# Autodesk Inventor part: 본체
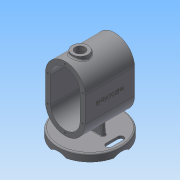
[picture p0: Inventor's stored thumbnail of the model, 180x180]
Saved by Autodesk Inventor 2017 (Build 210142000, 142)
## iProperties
Created: 2016-12
Part Number: 본체
Material: 알루미늄 6061
Document SubType Name: Modeling
Designer: mduedu
Density: 2.71 g/cm^3
Appearance: 기본값
Mass: 1098.88 g
Surface Area: 1080.91 cm^2
Volume: 405.491 cm^3
Author: mduedu
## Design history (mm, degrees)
sketch "스케치1"
  geometry: L1 (40, -25)-(40, 25); L2 (-40, 25)-(-40, -25); L3 (-40, -25)-(40, 25); L4 (40, -25)-(-40, 25); L5 (0, 25)-(0, -25); A1 r 40 centre (0, 25) between (40, 25) and (-40, 25); A2 r 40 centre (0, -25) between (-40, -25) and (40, -25); 1 further point
  constraints: 10 end point, 4 point on circle, 3 tangent, 2 centre point, 2 midpoint, 2 parallel, 1 vertical
  dimensions: "d0" = 130 dimension on A2 A1; "d2" = 80 distance between parallel lines of L1 L2
extrude "돌출1" new body sketch "스케치1" stored distance "d3" = 100; taper "d4" = 0 deg
feature "쉘1" dims "d5" = 10
sketch "스케치2"
  geometry: L1 (-75, 65)-(-90, 65); L2 (-90, 65)-(-90, 0); L3 (-75, 0)-(-75, 65); L4 (-75, 0)-(-90, 0); 1 further point
  constraints: 8 end point, 1 horizontal, 1 horizontal alignment, 1 parallel, 1 perpendicular
  dimensions: "d6" = 90 distance from line of L2 point (0, 0); "d83" = 15 distance of L1.start L1.end; "d84" = 130 diameter of L1 L4
revolve "회전1" sketch "스케치2" stored, may be unused: angle "d85" = 90 deg
fillet "모깎기5" dims "d86" = 3
hole "구멍6" diameter "d89" = 120; stored, may be unused: countersink angle "d93" = 90 deg, drill point angle "d95" = 0 deg; dims "d87" = 10, "d88" = 10, "d90" = 6, "d91" = 4, "d92" = 2, "d94" = 10
sketch "스케치15"
  geometry: L1 (-90, -60)-(-90, 60) reference; A1 r 21.75 centre (-105.75, 0) between (-90, -15) and (-90, 15); 3 further points
  constraints: 3 point on circle, 2 point on line, 1 centre point, 1 horizontal alignment, 1 midpoint
  dimensions: "d119" = 30 distance of A1.start A1.end; "d120" = 6 distance of point (-84, 0) point (-90, 0)
extrude "돌출6" cut sketch "스케치15" stored distance "d97" = 10; taper "d98" = 0 deg
sketch "스케치5"
  geometry: L1 (4, -30)-(-4, -30); L2 (-4, -30)-(-4, 30); L3 (-4, 30)-(4, 30); L4 (4, 30)-(4, -30); L5 (4, -30)-(-4, 30); L6 (-4, -30)-(4, 30); 3 further points
  constraints: 12 end point, 3 midpoint, 2 parallel, 1 coincident, 1 horizontal, 1 perpendicular
  dimensions: "d22" = 8 distance of L2.end L3.end; "d24" = 60 distance of L1.end L2.end
extrude "돌출3" join sketch "스케치5" stored distance "d25" = 80; taper "d26" = 0 deg
feature "면 기울기1" dims angle "d27" = 5 deg
sketch "스케치6"
  geometry: L1 (-28.115, -53.453)-(-30, -75); L2 (-62, -75)-(62, -75) reference; A1 r 40 centre (0, -25) between (-40, -25) and (40, -25) reference; 1 further point
  constraints: 2 end point, 1 point on circle, 1 point on line
  dimensions: "d28" = 30 horizontal distance of A1.centre L1.end; "d102" = 85 deg angle of L2 L1
feature "리브1" sketch "스케치6" dims "d30" = 1, "d31" = 8, "d32" = 0, "d33" = 0, "d34" = 1, "d35" = 1
fillet "모깎기2" dims "d36" = 3
fillet "모깎기3" dims "d37" = 1, "d38" = 1
node "작업 평면1"
sketch "스케치9"
  geometry: 1 further point
sketch "스케치7"
  geometry: L1 (40, 50)-(-40, 50) reference; C1 r 16 at (0, 20); 1 further point
  constraints: 1 centre point, 1 vertical alignment
  dimensions: "d40" = 32 diameter of C1; "d41" = 30 distance from line of C1.centre L1
extrude "돌출4" join sketch "스케치7" stored distance "d42" = 80; taper "d43" = 0 deg
hole "구멍2" diameter "d46" = 20; stored, may be unused: countersink angle "d50" = 90 deg, drill point angle "d52" = 118 deg; dims "d44" = 10, "d45" = 10, "d47" = 6, "d48" = 4, "d49" = 2, "d51" = 8
fillet "모깎기4" dims "d53" = 3
node "작업 평면2"
sketch "스케치8"
  geometry: C1 r 16 at (0, 0) reference; C2 r 15 at (0, 0); 1 further point
  constraints: 1 centre point, 1 coincident
  dimensions: "d55" = 30 diameter of C2
extrude "돌출5" cut sketch "스케치8" stored distance "d56" = 80; taper "d57" = 0 deg
chamfer "모따기1" distance "d58" = 1; stored, may be unused: second distance "d59" = 2, angle "d60" = 45 deg
sketch "스케치10"
  geometry: 2 further points
  constraints: 1 coincident, 1 other
feature "엠보싱1" sketch "스케치10" dims "d0" = 130, "d2" = 80, "d61" = 0.5, "d62" = 0
sketch "스케치11"
  geometry: 1 further point
hole "구멍3" sketch "스케치11" at (0, 60) diameter "d63" = 3.242; stored, may be unused: countersink angle "d67" = 90 deg, drill point angle "d69" = 120 deg; dims "d64" = 8.6, "d65" = 4, "d66" = 2, "d68" = 10.6
sketch "스케치12"
  geometry: 1 further point
hole "구멍5" sketch "스케치12" at (0, 60) diameter "d70" = 3.242; stored, may be unused: countersink angle "d74" = 90 deg, drill point angle "d76" = 120 deg; dims "d71" = 8.6, "d72" = 4, "d73" = 2, "d75" = 10.6
sketch "스케치16"
  geometry: L1 (0, 0)-(0, 50); L2 (-56, 12)-(-56, -12); L3 (-44, 12)-(-44, -12); L4 (-50, -12)-(-50, 12); A1 r 50 centre (0, 0) between (0, 50) and (-50, 0); A2 r 6 centre (-50, 12) between (-44, 12) and (-56, 12); A3 r 6 centre (-50, -12) between (-56, -12) and (-44, -12); 1 further point
  constraints: 8 end point, 6 point on circle, 4 tangent, 3 centre point, 3 parallel, 1 coincident, 1 equal radius, 1 horizontal alignment, 1 midpoint, 1 vertical
  dimensions: "d103" = 100 diameter of A1; "d121" = 6 radius of A2; "d122" = 24 distance of L4.start L4.end
extrude "돌출7" cut sketch "스케치16" stored distance "d123" = 10; taper "d124" = 0 deg
node "솔리드1"
pattern_circular "원형 패턴1" dims angle "d100" = 90 deg
mirror "대칭1"
pattern_linear "직사각형 패턴1"
pattern_linear "직사각형 패턴2"
mirror "대칭2"
sketch "스케치13"
  geometry: L1 (-40, 25)-(-40, -25) reference; L2 (40, -25)-(40, 25) reference; L3 (35, 25)-(35, -25); L4 (-35, -25)-(-35, 25); A1 r 40 centre (0, 25) between (40, 25) and (-40, 25) reference; A2 r 40 centre (0, -25) between (-40, -25) and (40, -25) reference; A3 r 35 centre (0, 25) between (35, 25) and (-35, 25); A4 r 35 centre (0, -25) between (-35, -25) and (35, -25); 2 further points
  constraints: 5 point on circle, 4 end point, 2 centre point, 3 other
  dimensions: "d77" = 5 distance between parallel lines of L3 L2
sketch "스케치14"
  geometry: L1 (-40, 25)-(-40, -25) reference; L2 (40, -25)-(40, 25) reference; L3 (35, 25)-(35, -25); L4 (-35, -25)-(-35, 25); A1 r 40 centre (0, 25) between (40, 25) and (-40, 25) reference; A2 r 40 centre (0, -25) between (-40, -25) and (40, -25) reference; A3 r 35 centre (0, 25) between (35, 25) and (-35, 25); A4 r 35 centre (0, -25) between (-35, -25) and (35, -25); 2 further points
  constraints: 5 point on circle, 4 end point, 2 centre point, 3 other
  dimensions: "d80" = 5 distance between parallel lines of L2 L3
